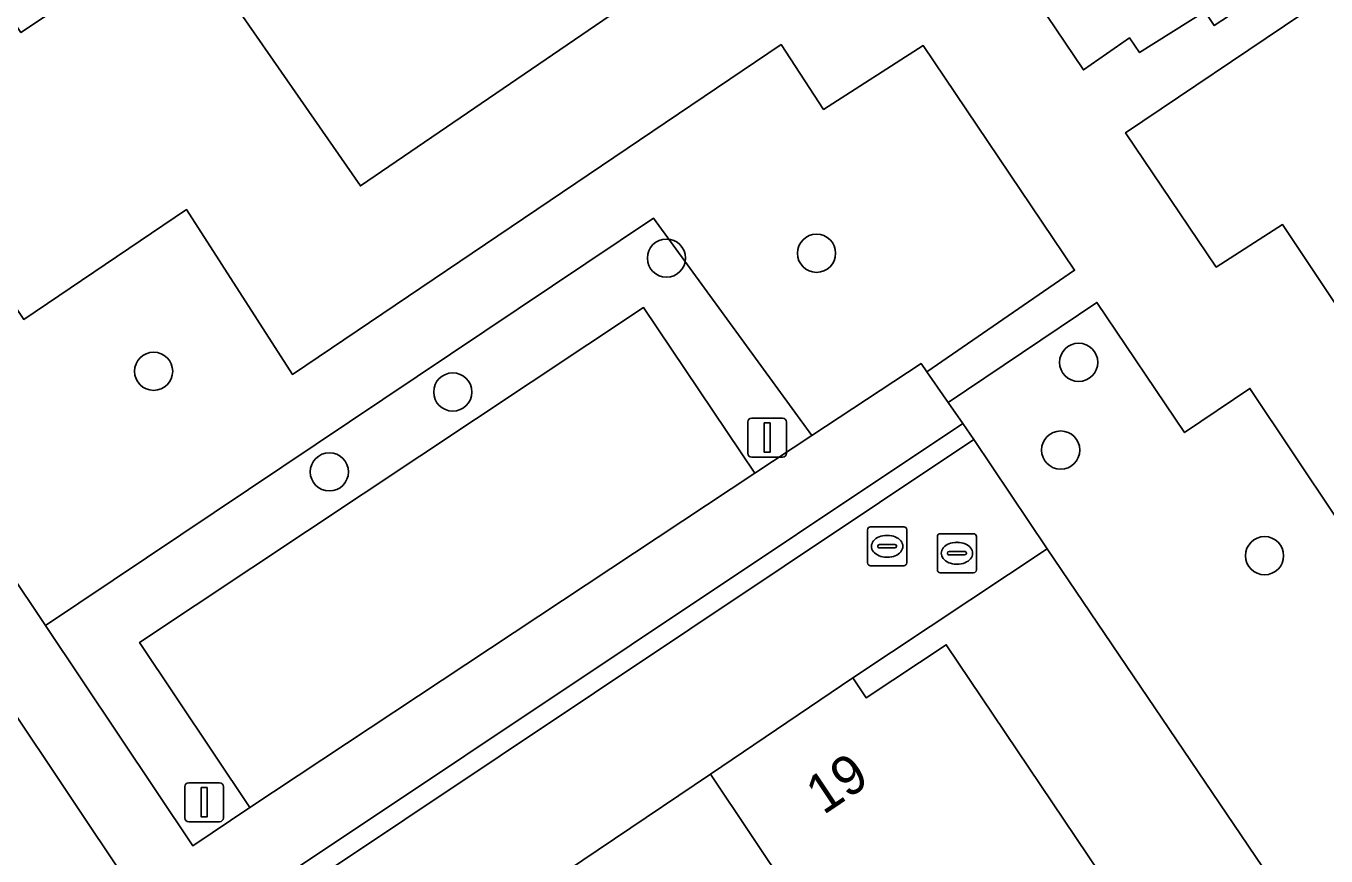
# Model space of a CAD drawing. Extents: x 158793 to 159888, y 384317 to 385256.
# Drawn here: x 159170.74 to 159204.02, y 384561.36 to 384582.61 of the extents above; entities that cross this region are included whole.
import ezdxf

# ---------------------------------------------------------------- set-up
doc = ezdxf.new("R2010")
doc.units = 0
for name, color, linetype in [('IMGEO_Boom', 7, 'Continuous'), ('IMGEO_Erf', 7, 'Continuous'), ('IMGEO_Groenvoorziening', 7, 'Continuous'), ('IMGEO_Haag', 7, 'Continuous'), ('IMGEO_Lichtmast', 7, 'Continuous'), ('IMGEO_Pand', 7, 'Continuous'), ('IMGEO_Pand_nummerreeks', 7, 'Continuous'), ('IMGEO_Parkeervlak_open', 7, 'Continuous'), ('IMGEO_Rijbaan_lokaal_open', 7, 'Continuous'), ('IMGEO_Rioolput', 7, 'Continuous'), ('IMGEO_Voetpad_gesloten', 7, 'Continuous'), ('IMGEO_Voetpad_open', 7, 'Continuous')]:
    doc.layers.add(name, color=color, linetype=linetype)

msp = doc.modelspace()

# ---------------------------------------------------------------- linework, layer by layer
at = {"layer": 'IMGEO_Boom'}
for centre in [(159190.976, 384576.789), (159187.135, 384576.663), (159174.003, 384573.767), (159197.688, 384573.995), (159181.664, 384573.236), (159197.228, 384571.749), (159178.503, 384571.191), (159202.448, 384569.045)]:
    msp.add_circle(centre, 0.489, dxfattribs=at)
at = {"layer": 'IMGEO_Erf'}
for points in [[(159203.688, 384559.176), (159196.883, 384569.224), (159191.903, 384565.914), (159192.245, 384565.407), (159194.299, 384566.763), (159199.128, 384559.588)], [(159170.24, 384558.583), (159173.398, 384560.595), (159168.665, 384567.656)]]:
    msp.add_lwpolyline(points, dxfattribs=at)
at = {"layer": 'IMGEO_Groenvoorziening'}
for points in [[(159184.844, 384610.474), (159149.937, 384586.778), (159139.375, 384579.667), (159141.123, 384576.932), (159150.625, 384583.433), (159151.747, 384581.759), (159165.041, 384590.724), (159170.605, 384582.437), (159174.689, 384585.159), (159179.297, 384578.512), (159193.347, 384588.107), (159197.808, 384581.483), (159198.988, 384582.307), (159199.249, 384581.925), (159200.917, 384582.98), (159201.158, 384582.618), (159202.847, 384583.73), (159200.329, 384587.446), (159199.667, 384588.43)], [(159174.848, 384577.908), (159170.678, 384575.093), (159165.114, 384583.512), (159164.29, 384582.941), (159163.188, 384584.508), (159154.051, 384578.453), (159155.852, 384575.778), (159162.529, 384580.264), (159171.232, 384567.261), (159186.801, 384577.691), (159190.856, 384572.121), (159193.655, 384573.965), (159193.8, 384573.756), (159197.584, 384576.354), (159193.706, 384582.105), (159191.156, 384580.471), (159190.067, 384582.131), (159177.557, 384573.685)], [(159194.349, 384572.964), (159194.721, 384572.428), (159195.001, 384572.021), (159196.883, 384569.224), (159203.688, 384559.176), (159205.614, 384556.297), (159212.583, 384560.985), (159215.457, 384562.919), (159216.603, 384561.19), (159220.224, 384555.79), (159241.676, 384570.148), (159236.203, 384578.24), (159225.432, 384570.963), (159220.412, 384578.373), (159205.406, 384568.333), (159202.072, 384573.326), (159200.399, 384572.198), (159198.155, 384575.531)], [(159186.547, 384575.396), (159189.399, 384571.161), (159190.856, 384572.121), (159186.801, 384577.691), (159171.232, 384567.261), (159175.007, 384561.62), (159176.47, 384562.598), (159173.643, 384566.823)]]:
    msp.add_lwpolyline(points, close=True, dxfattribs=at)
msp.add_lwpolyline([(159203.401, 384582.912), (159198.891, 384579.876), (159201.209, 384576.434), (159202.909, 384577.523), (159204.542, 384575.066), (159207.013, 384576.713), (159208.686, 384574.19), (159223.666, 384584.415), (159228.726, 384576.872), (159242.691, 384586.237)], dxfattribs=at)
at = {"layer": 'IMGEO_Haag'}
msp.add_lwpolyline([(159173.643, 384566.823), (159186.547, 384575.396), (159189.399, 384571.161), (159190.856, 384572.121), (159186.801, 384577.691), (159171.232, 384567.261), (159175.007, 384561.62), (159176.47, 384562.598)], close=True, dxfattribs=at)
at = {"layer": 'IMGEO_Lichtmast'}
for p, q in [((159189.317, 384572.568), (159190.107, 384572.568)), ((159190.107, 384572.568), (159189.317, 384572.568)), ((159189.217, 384571.668), (159189.217, 384572.468)), ((159189.217, 384572.468), (159189.217, 384571.668)), ((159190.207, 384572.468), (159190.207, 384571.668)), ((159190.207, 384571.668), (159190.207, 384572.468)), ((159190.107, 384571.568), (159189.317, 384571.568)), ((159189.317, 384571.568), (159190.107, 384571.568)), ((159174.802, 384562.332), (159174.802, 384563.132)), ((159174.802, 384563.132), (159174.802, 384562.332)), ((159174.902, 384563.232), (159175.692, 384563.232)), ((159175.692, 384563.232), (159174.902, 384563.232)), ((159175.792, 384563.132), (159175.792, 384562.332)), ((159175.792, 384562.332), (159175.792, 384563.132)), ((159175.692, 384562.232), (159174.902, 384562.232)), ((159174.902, 384562.232), (159175.692, 384562.232))]:
    msp.add_line(p, q, dxfattribs=at)
for points in [[(159189.637, 384572.443), (159189.787, 384572.443), (159189.787, 384571.693), (159189.637, 384571.693), (159189.637, 384572.443)], [(159175.222, 384563.107), (159175.372, 384563.107), (159175.372, 384562.357), (159175.222, 384562.357), (159175.222, 384563.107)]]:
    msp.add_lwpolyline(points, dxfattribs=at)
for centre, start, end in [((159189.317, 384572.468), 90, 180), ((159189.317, 384572.468), 90, 180), ((159190.107, 384572.468), 0, 90), ((159190.107, 384572.468), 360, 90), ((159189.317, 384571.668), 180, 270), ((159189.317, 384571.668), 180, 270), ((159190.107, 384571.668), 270, 0), ((159190.107, 384571.668), 270, 0), ((159174.902, 384563.132), 90, 180), ((159174.902, 384563.132), 90, 180), ((159175.692, 384563.132), 0, 90), ((159175.692, 384563.132), 360, 90), ((159174.902, 384562.332), 180, 270), ((159174.902, 384562.332), 180, 270), ((159175.692, 384562.332), 270, 0), ((159175.692, 384562.332), 270, 0)]:
    msp.add_arc(centre, 0.1, start, end, dxfattribs=at)
at = {"layer": 'IMGEO_Pand'}
for points in [[(159194.299, 384566.763), (159192.245, 384565.407), (159191.903, 384565.914), (159188.261, 384563.455), (159194.41, 384554.261), (159199.588, 384557.723), (159198.584, 384559.214), (159199.128, 384559.588)], [(159188.261, 384563.455), (159184.571, 384560.964), (159184.908, 384560.47), (159182.886, 384559.116), (159187.697, 384551.937), (159188.227, 384552.291), (159189.232, 384550.798), (159194.41, 384554.261)]]:
    msp.add_lwpolyline(points, close=True, dxfattribs=at)
at = {"layer": 'IMGEO_Parkeervlak_open'}
msp.add_lwpolyline([(159189.399, 384571.161), (159186.547, 384575.396), (159173.643, 384566.823), (159176.47, 384562.598)], close=True, dxfattribs=at)
at = {"layer": 'IMGEO_Rijbaan_lokaal_open'}
msp.add_lwpolyline([(159119.692, 384548.604), (159118.029, 384551.058), (159117.766, 384551.476), (159117.718, 384551.55), (159112.692, 384559.025), (159112.208, 384559.697), (159111.807, 384559.428), (159111.782, 384559.411), (159131.797, 384529.704), (159178.017, 384560.678), (159195.001, 384572.021), (159194.721, 384572.428), (159177.742, 384561.091), (159131.92, 384530.403), (159130.515, 384532.465), (159130.239, 384532.89), (159123.806, 384542.482)], close=True, dxfattribs=at)
msp.add_lwpolyline([(159211.83, 384541.696), (159201.909, 384535.023), (159197.999, 384532.399), (159196.883, 384531.677), (159196.033, 384531.127), (159195.59, 384530.821), (159178.371, 384556.579), (159178.788, 384556.84), (159178.669, 384557.017), (159179.615, 384557.65), (159184.571, 384560.964), (159188.261, 384563.455), (159191.903, 384565.914), (159196.883, 384569.224), (159195.001, 384572.021), (159178.017, 384560.678), (159131.797, 384529.704), (159111.782, 384559.411), (159108.917, 384557.49), (159163.183, 384476.655), (159166.119, 384478.572), (159153.048, 384498.068), (159198.654, 384528.669), (159243.562, 384558.734)], dxfattribs=at)
at = {"layer": 'IMGEO_Rioolput'}
for p, q in [((159192.284, 384568.859), (159192.284, 384569.711)), ((159192.359, 384569.785), (159193.211, 384569.785)), ((159192.772, 384569.565), (159192.797, 384569.565)), ((159193.285, 384569.711), (159193.285, 384568.859)), ((159194.145, 384569.607), (159194.997, 384569.607)), ((159192.543, 384569.279), (159192.543, 384569.291)), ((159192.981, 384569.242), (159192.583, 384569.242)), ((159192.586, 384569.328), (159192.984, 384569.328)), ((159193.027, 384569.291), (159193.027, 384569.279)), ((159194.07, 384568.681), (159194.07, 384569.533)), ((159194.558, 384569.387), (159194.583, 384569.387)), ((159195.071, 384569.533), (159195.071, 384568.681)), ((159192.795, 384569.005), (159192.77, 384569.005)), ((159194.329, 384569.101), (159194.329, 384569.113)), ((159194.767, 384569.064), (159194.369, 384569.064)), ((159194.372, 384569.15), (159194.77, 384569.15)), ((159194.813, 384569.113), (159194.813, 384569.101)), ((159193.211, 384568.785), (159192.359, 384568.785)), ((159194.997, 384568.607), (159194.145, 384568.607)), ((159194.581, 384568.827), (159194.556, 384568.827))]:
    msp.add_line(p, q, dxfattribs=at)
for points in [[(159192.284, 384568.859), (159192.284, 384569.711)], [(159192.359, 384569.785), (159193.211, 384569.785)], [(159193.285, 384569.711), (159193.285, 384568.859)], [(159194.145, 384569.607), (159194.997, 384569.607)], [(159194.07, 384568.681), (159194.07, 384569.533)], [(159195.071, 384569.533), (159195.071, 384568.681)], [(159193.211, 384568.785), (159192.359, 384568.785)], [(159194.997, 384568.607), (159194.145, 384568.607)]]:
    msp.add_lwpolyline(points, dxfattribs=at)
for centre, radius, start, end in [((159192.361, 384569.709), 0.0765, 91.552, 178.448), ((159192.361, 384569.709), 0.0765, 91.552, 178.448), ((159193.209, 384569.709), 0.0765, 1.552, 88.448), ((159193.209, 384569.709), 0.0765, 1.552, 88.448), ((159194.147, 384569.531), 0.0765, 91.552, 178.448), ((159194.147, 384569.531), 0.0765, 91.552, 178.448), ((159194.995, 384569.531), 0.0765, 1.552, 88.448), ((159194.995, 384569.531), 0.0765, 1.552, 88.448), ((159192.583, 384569.288), 0.0403, 85.8775, 175.7526), ((159192.58, 384569.278), 0.0366, 178.938, 274.7102), ((159192.984, 384569.285), 0.043, 264.8664, 352.4533), ((159192.988, 384569.29), 0.0386, 1.7309, 96.639), ((159194.369, 384569.11), 0.0403, 85.8775, 175.7526), ((159194.366, 384569.1), 0.0366, 178.938, 274.7102), ((159194.77, 384569.107), 0.043, 264.8664, 352.4533), ((159194.774, 384569.112), 0.0386, 1.7309, 96.639), ((159192.361, 384568.861), 0.0765, 181.552, 268.448), ((159192.361, 384568.861), 0.0765, 181.552, 268.448), ((159193.209, 384568.861), 0.0765, 271.552, 358.448), ((159193.209, 384568.861), 0.0765, 271.552, 358.448), ((159194.147, 384568.683), 0.0765, 181.552, 268.448), ((159194.147, 384568.683), 0.0765, 181.552, 268.448), ((159194.995, 384568.683), 0.0765, 271.552, 358.448), ((159194.995, 384568.683), 0.0765, 271.552, 358.448)]:
    msp.add_arc(centre, radius, start, end, dxfattribs=at)
for centre, major_axis, ratio, start_param, end_param in [((159192.771, 384569.285), (-0.387, 0.002), 0.722429, 4.712389, 7.853982), ((159192.796, 384569.285), (-0.39, 0.002), 0.717154, 1.570796, 4.712389), ((159194.557, 384569.107), (-0.387, 0.002), 0.722429, 4.712389, 7.853982), ((159194.582, 384569.107), (-0.39, 0.002), 0.717154, 1.570796, 4.712389)]:
    msp.add_ellipse(centre, major_axis=major_axis, ratio=ratio, start_param=start_param, end_param=end_param, dxfattribs=at)
at = {"layer": 'IMGEO_Voetpad_gesloten'}
for points in [[(159200.917, 384582.98), (159199.249, 384581.925), (159198.988, 384582.307), (159197.808, 384581.483), (159193.347, 384588.107), (159179.297, 384578.512), (159174.689, 384585.159), (159170.605, 384582.437), (159165.041, 384590.724), (159151.747, 384581.759), (159150.625, 384583.433), (159141.123, 384576.932), (159139.375, 384579.667), (159138.377, 384581.17), (159122.57, 384570.491)], [(159242.691, 384586.237), (159228.726, 384576.872), (159223.666, 384584.415), (159208.686, 384574.19), (159207.013, 384576.713), (159204.542, 384575.066), (159202.909, 384577.523), (159201.209, 384576.434), (159198.891, 384579.876), (159203.401, 384582.912)], [(159165.114, 384583.512), (159170.678, 384575.093), (159174.848, 384577.908), (159177.557, 384573.685), (159190.067, 384582.131), (159191.156, 384580.471), (159193.706, 384582.105), (159197.584, 384576.354), (159193.8, 384573.756), (159194.349, 384572.964), (159198.155, 384575.531), (159200.399, 384572.198), (159202.072, 384573.326), (159205.406, 384568.333)]]:
    msp.add_lwpolyline(points, dxfattribs=at)
at = {"layer": 'IMGEO_Voetpad_open'}
for points in [[(159177.742, 384561.091), (159194.721, 384572.428), (159194.349, 384572.964), (159193.8, 384573.756), (159193.655, 384573.965), (159190.856, 384572.121), (159189.399, 384571.161), (159176.47, 384562.598), (159175.007, 384561.62), (159171.232, 384567.261), (159162.529, 384580.264), (159155.852, 384575.778), (159154.128, 384574.62), (159124.093, 384554.441), (159117.376, 384564.452), (159116.454, 384565.827), (159111.43, 384562.409)], [(159168.665, 384567.656), (159173.398, 384560.595), (159170.24, 384558.583)]]:
    msp.add_lwpolyline(points, dxfattribs=at)

# ---------------------------------------------------------------- texts
at = {"layer": 'IMGEO_Pand_nummerreeks'}
msp.add_text('19', height=1, rotation=33.8274, dxfattribs=at).set_placement((159191.151, 384562.394))

doc.saveas('drawing.dxf')
